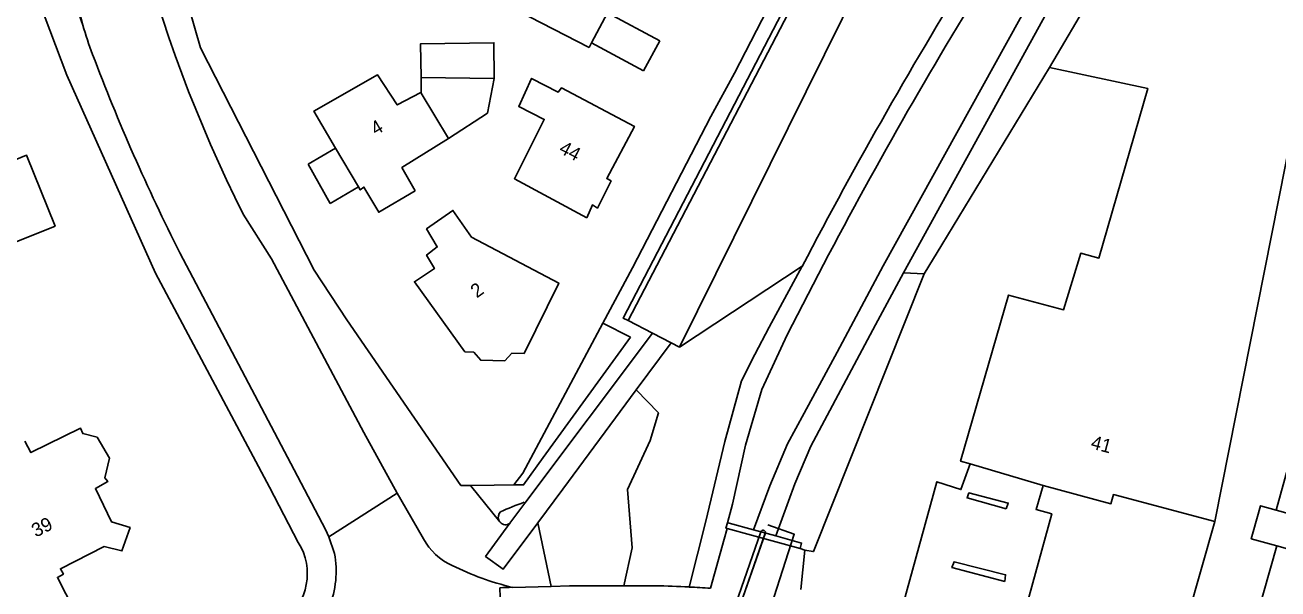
# Model space of a CAD drawing. Extents: x 194485 to 197793, y 468269 to 470822.
# Drawn here: x 194667.8 to 194777.6, y 470049.6 to 470099 of the extents above; entities that cross this region are included whole.
import ezdxf

# ---------------------------------------------------------------- set-up
doc = ezdxf.new("R2010")
doc.units = 0
for name, color, linetype in [('BGT grensvlak begroeid terreindeel', 7, 'Continuous'), ('BGT grensvlak gebouwinstallatie plus 1', 7, 'Continuous'), ('BGT grensvlak kunstwerkdeel uitbreiding populatie min 1', 7, 'Continuous'), ('BGT grensvlak onbegroeid terreindeel', 7, 'Continuous'), ('BGT grensvlak ondersteunend waterdeel LR', 7, 'Continuous'), ('BGT grensvlak pand op maaiveld', 7, 'Continuous'), ('BGT grensvlak scheiding', 7, 'Continuous'), ('BGT grensvlak waterdeel', 7, 'Continuous'), ('BGT grensvlak wegdeel', 7, 'Continuous'), ('BGT lijnelement kunstwerkdeel uitbreiding populatie duiker', 7, 'Continuous'), ('BGT tekst huisnummerreeks', 7, 'Continuous')]:
    doc.layers.add(name, color=color, linetype=linetype)

msp = doc.modelspace()

# ---------------------------------------------------------------- linework, layer by layer
at = {"layer": 'BGT grensvlak begroeid terreindeel'}
msp.add_line((194725.17, 470070.76), (194735.93, 470077.85), dxfattribs=at)
msp.add_lwpolyline([(194720.29, 470049.82), (194721, 470053.17), (194720.61, 470058.28), (194722.58, 470062.58), (194723.32, 470064.99), (194721.36, 470067)], dxfattribs=at)
at = {"layer": 'BGT grensvlak gebouwinstallatie plus 1'}
for p, q in [((194723.44, 470097.62), (194718.86, 470100.08)), ((194717.45, 470097.44), (194722.02, 470094.98)), ((194722.02, 470094.98), (194723.44, 470097.62)), ((194702.52, 470094.4), (194702.52, 470093.04)), ((194708.34, 470091.28), (194708.92, 470094.31)), ((194704.9, 470089.04), (194708.34, 470091.28)), ((194695.01, 470088.22), (194692.6, 470086.81)), ((194692.6, 470086.81), (194694.52, 470083.36)), ((194694.52, 470083.36), (194697.01, 470084.82))]:
    msp.add_line(p, q, dxfattribs=at)
msp.add_lwpolyline([(194757.04, 470058.61), (194756.43, 470056.53), (194757.8, 470056.13), (194754.93, 470045.73), (194744.79, 470048.32), (194747.73, 470058.95), (194749.83, 470058.27), (194750.64, 470060.52)], dxfattribs=at)
at = {"layer": 'BGT grensvlak kunstwerkdeel uitbreiding populatie min 1'}
msp.add_lwpolyline([(194724.26, 470031.41), (194732.3, 470054.57), (194732.32, 470054.6), (194732.34, 470054.64), (194732.37, 470054.66), (194732.4, 470054.68), (194732.44, 470054.7), (194732.48, 470054.7), (194732.52, 470054.7), (194732.56, 470054.69), (194732.59, 470054.67), (194732.62, 470054.65), (194732.65, 470054.62), (194732.67, 470054.59), (194732.69, 470054.55), (194732.69, 470054.51), (194732.69, 470054.47), (194732.68, 470054.44), (194724.64, 470031.28)], dxfattribs=at)
at = {"layer": 'BGT grensvlak onbegroeid terreindeel'}
msp.add_line((194736.91, 470052.85), (194746.62, 470077.18), dxfattribs=at)
for points in [[(194757.6, 470095.27), (194748.16, 470079.72), (194746.62, 470077.18)], [(194718.45, 470072.86), (194711.44, 470059.71), (194710.63, 470058.67)], [(194753.79, 470056.57), (194753.98, 470057.08), (194750.54, 470057.97), (194750.37, 470057.53), (194753.79, 470056.57)], [(194736.15, 470052.96), (194736.88, 470052.83), (194736.91, 470052.85)], [(194753.7, 470050.2), (194753.75, 470050.8), (194749.24, 470051.94), (194749.05, 470051.44), (194753.7, 470050.2)]]:
    msp.add_lwpolyline(points, dxfattribs=at)
at = {"layer": 'BGT grensvlak ondersteunend waterdeel LR'}
msp.add_line((194744.81, 470077.26), (194746.62, 470077.18), dxfattribs=at)
at = {"layer": 'BGT grensvlak pand op maaiveld'}
for p, q in [((194757.6, 470095.27), (194762.34, 470103.37)), ((194717.45, 470097.44), (194718.86, 470100.08)), ((194717.23, 470097.03), (194717.45, 470097.44)), ((194702.52, 470094.4), (194708.92, 470094.31)), ((194704.9, 470089.04), (194702.52, 470093.04)), ((194695.01, 470088.22), (194697.01, 470084.82)), ((194711.53, 470070.2), (194710.45, 470070.23)), ((194757.04, 470058.61), (194750.64, 470060.52))]:
    msp.add_line(p, q, dxfattribs=at)
for points in [[(194718.86, 470100.08), (194712.57, 470103.25), (194711, 470100.25), (194717.23, 470097.03)], [(194708.92, 470094.31), (194708.89, 470097.45), (194702.45, 470097.35), (194702.52, 470094.4)], [(194750.64, 470060.52), (194749.8, 470060.77), (194754.02, 470075.32), (194758.83, 470074.04), (194760.34, 470078.99), (194761.94, 470078.57), (194766.22, 470093.45), (194757.6, 470095.27)], [(194702.52, 470093.04), (194702.49, 470093.08), (194700.42, 470092), (194698.67, 470094.64), (194693.11, 470091.46), (194695.01, 470088.22)], [(194717.03, 470082.11), (194717.52, 470083.23), (194717.97, 470082.95), (194719.17, 470085.34), (194718.79, 470085.54), (194721.21, 470090.12), (194714.82, 470093.5), (194714.53, 470093.13), (194712.2, 470094.32), (194711.07, 470091.85), (194713.31, 470090.72), (194710.69, 470085.52), (194717.03, 470082.11)], [(194701.99, 470084.47), (194700.83, 470086.51), (194704.9, 470089.04)], [(194778.61, 470088.47), (194778.31, 470086.88), (194772.09, 470055.46)], [(194666.76, 470074.86), (194664.92, 470079.18), (194670.42, 470081.37), (194667.9, 470087.6), (194664.34, 470086.13), (194664.56, 470085.52), (194659.8, 470083.49), (194661.95, 470078.2), (194656.62, 470075.8)], [(194697.01, 470084.82), (194697.17, 470084.54), (194697.49, 470084.79), (194698.8, 470082.58), (194701.99, 470084.47)], [(194707.13, 470070.32), (194706.35, 470070.34), (194701.92, 470076.49), (194703.67, 470077.65), (194702.99, 470078.83), (194703.93, 470079.55), (194702.99, 470081.13), (194705.29, 470082.75), (194706.93, 470080.4), (194714.57, 470076.37), (194711.53, 470070.2)], [(194707.13, 470070.32), (194707.73, 470069.61), (194709.84, 470069.55), (194710.45, 470070.23)], [(194667.77, 470062.52), (194668.3, 470061.51), (194672.65, 470063.65), (194672.84, 470063.17), (194674.1, 470062.86), (194675.19, 470061.03), (194674.79, 470059.29), (194675.04, 470058.96), (194673.96, 470058.36), (194675.35, 470055.44), (194676.99, 470054.94), (194676.27, 470052.89), (194674.73, 470053.26), (194670.89, 470051.33), (194671.15, 470050.86), (194670.62, 470050.56), (194672.08, 470047.7), (194668.09, 470045.68), (194666.81, 470048.59)], [(194667.77, 470062.52), (194668.3, 470061.51), (194672.65, 470063.65), (194672.84, 470063.17), (194674.1, 470062.86), (194675.19, 470061.03), (194674.79, 470059.29), (194675.04, 470058.96), (194673.96, 470058.36), (194675.35, 470055.44), (194676.99, 470054.94), (194676.27, 470052.89), (194674.73, 470053.26), (194670.89, 470051.33), (194671.15, 470050.86), (194670.62, 470050.56), (194672.08, 470047.7), (194668.09, 470045.68), (194666.81, 470048.59)], [(194772.09, 470055.46), (194763.2, 470057.83), (194762.98, 470057.03), (194757.04, 470058.61)]]:
    msp.add_lwpolyline(points, dxfattribs=at)
at = {"layer": 'BGT grensvlak scheiding'}
for p, q in [((194735.75, 470053.1), (194729.35, 470054.84)), ((194731.66, 470054.73), (194733.61, 470054.2))]:
    msp.add_line(p, q, dxfattribs=at)
for points in [[(194729.37, 470055.36), (194729.23, 470054.87), (194729.35, 470054.84)], [(194731.66, 470054.73), (194729.51, 470055.32), (194729.37, 470055.36)], [(194733.61, 470054.2), (194735.87, 470053.57), (194735.75, 470053.1)]]:
    msp.add_lwpolyline(points, dxfattribs=at)
at = {"layer": 'BGT grensvlak waterdeel'}
for p, q in [((194743.02, 470077.9), (194763.1, 470114.14)), ((194744.81, 470077.26), (194764.66, 470113.36))]:
    msp.add_line(p, q, dxfattribs=at)
for points in [[(194731.66, 470054.73), (194733.07, 470058.6), (194734.63, 470062.27), (194736.08, 470064.98), (194739, 470070.33), (194743.02, 470077.9)], [(194733.61, 470054.2), (194735.27, 470058.78), (194736.68, 470062.08), (194739.3, 470067.01), (194742.35, 470072.72), (194744.81, 470077.26)]]:
    msp.add_lwpolyline(points, dxfattribs=at)
at = {"layer": 'BGT grensvlak wegdeel'}
for p, q in [((194672.85, 470099), (194668.91, 470115.35)), ((194777.47, 470056.47), (194785.35, 470085.04)), ((194681.36, 470079.02), (194691.38, 470060)), ((194681.36, 470079.02), (194691.38, 470060)), ((194696.01, 470073.14), (194705.98, 470058.61)), ((194718.45, 470072.86), (194720.86, 470071.62)), ((194720.66, 470073.08), (194722.8, 470071.98)), ((194711.6, 470057.08), (194722.8, 470071.98)), ((194713.22, 470061.09), (194720.86, 470071.62)), ((194722.8, 470071.98), (194724.43, 470071.14)), ((194721.36, 470067), (194724.43, 470071.14)), ((194724.43, 470071.14), (194725.17, 470070.76)), ((194714.94, 470058.29), (194721.36, 470067)), ((194697.5, 470063.28), (194700.41, 470057.94)), ((194691.74, 470053.62), (194689.22, 470058.48)), ((194691.74, 470053.62), (194689.22, 470058.48)), ((194705.98, 470058.61), (194706.85, 470058.62)), ((194706.85, 470058.62), (194708.9, 470058.65)), ((194706.85, 470058.62), (194709.4, 470055.44)), ((194708.9, 470058.65), (194710.63, 470058.67)), ((194700.41, 470057.94), (194694.43, 470054.13)), ((194712.75, 470055.36), (194714.94, 470058.29)), ((194711.6, 470057.08), (194710.3, 470055.32)), ((194711.55, 470057.16), (194711.6, 470057.08)), ((194777.47, 470056.47), (194781.08, 470055.45)), ((194709.4, 470055.44), (194709.42, 470055.4)), ((194713.92, 470049.78), (194712.75, 470055.36)), ((194727.46, 470055.5), (194726.01, 470049.72)), ((194772.09, 470055.46), (194768.7, 470043.52)), ((194694.43, 470054.13), (194694.91, 470052.66)), ((194694.43, 470054.13), (194694.91, 470052.66)), ((194736.15, 470052.96), (194735.75, 470053.1)), ((194735.79, 470049.49), (194736.15, 470052.96)), ((194777.54, 470053.33), (194774.58, 470042.9)), ((194777.54, 470053.33), (194780.27, 470052.57)), ((194709.43, 470048.84), (194709.4, 470049.65)), ((194713.92, 470049.78), (194710.51, 470049.69))]:
    msp.add_line(p, q, dxfattribs=at)
for points in [[(194696.01, 470073.14), (194693.13, 470077.51), (194683.18, 470096.99), (194679.88, 470108.39), (194679.16, 470111.8), (194677.42, 470121.59), (194676.5, 470131.68), (194676.34, 470138.79), (194676.65, 470148.24), (194677.32, 470157.81), (194678.33, 470164.6), (194679.43, 470173.22), (194681.09, 470183.46), (194683.7, 470197.19), (194687.3, 470213.24), (194688.11, 470217.15), (194690.16, 470224.82), (194693.77, 470236.11), (194697.78, 470246.83), (194699.13, 470250), (194709.7, 470275.65), (194716.32, 470292.04), (194723.12, 470308.96)], [(194718.45, 470072.86), (194721.03, 470077.72), (194727.92, 470090.98), (194729.99, 470094.77), (194749.21, 470132.1)], [(194720.66, 470073.08), (194739.39, 470109.08), (194744.75, 470119.44), (194751.26, 470132.02)], [(194725.17, 470070.76), (194744.22, 470109.24), (194744.59, 470109.08)], [(194737.5, 470106.52), (194720.21, 470073.31), (194720.66, 470073.08)], [(194669.47, 470099.86), (194671.46, 470094.6), (194679.21, 470077.25), (194689.22, 470058.48)], [(194669.47, 470099.86), (194671.46, 470094.6), (194679.21, 470077.25), (194689.22, 470058.48)], [(194697.5, 470063.28), (194689.38, 470078.51), (194686.91, 470082.41)], [(194727.46, 470055.5), (194729.14, 470062.48), (194730.59, 470067.81), (194731.77, 470070.11), (194733.01, 470072.52), (194735.93, 470077.85)], [(194737.35, 470077.15), (194734.59, 470071.84), (194732.39, 470067.05), (194730.95, 470062.17), (194729.81, 470056.98), (194729.37, 470055.36)], [(194713.22, 470061.09), (194711.49, 470058.68), (194710.88, 470058.67), (194710.63, 470058.67)], [(194691.38, 470060), (194694.13, 470054.76), (194694.43, 470054.13)], [(194691.38, 470060), (194694.13, 470054.76), (194694.43, 470054.13)], [(194702.71, 470053.95), (194701.18, 470056.65), (194700.41, 470057.94)], [(194777.47, 470056.47), (194776.11, 470056.85), (194775.46, 470054.56), (194775.29, 470053.96), (194777.54, 470053.33)], [(194710.3, 470055.32), (194708.16, 470052.41), (194709.7, 470051.28), (194712.75, 470055.36)], [(194727.87, 470049.61), (194729.08, 470053.93), (194729.35, 470054.84)], [(194720.29, 470049.82), (194715.52, 470049.83), (194713.92, 470049.78)], [(194720.29, 470049.82), (194723.07, 470049.82), (194723.04, 470049.82)]]:
    msp.add_lwpolyline(points, dxfattribs=at)
for centre, radius, start, end in [((194799.24, 470138.71), 125.65, 182.0727, 206.6229), ((194652.66, 470092.29), 21.27, 18.3828, 40.9739), ((194652.66, 470092.29), 21.27, 18.3828, 40.9739), ((195095, 469890.79), 404.87, 148.1238, 152.4834), ((195094.63, 469891), 402.87, 148.1205, 152.4789), ((194704.49, 470108.02), 32.9, 195.9054, 200.6591), ((194704.49, 470108.02), 32.9, 195.9054, 200.6591), ((194840.28, 470159.36), 178.07, 200.702, 206.8188), ((194840.28, 470159.36), 178.07, 200.702, 206.8188), ((194709.97, 470055.84), 0.701, 136.803, 201.9763), ((194720.73, 470031.23), 27.5, 109.4944, 114.1933), ((194709.92, 470055.82), 0.646, 202.2929, 216.578), ((194709.91, 470055.82), 0.636, 220.4622, 308.2072), ((194687.4, 470050.88), 5.13, 306.612, 32.2547), ((194687.4, 470050.88), 5.13, 306.612, 32.2547), ((194707.49, 470056.55), 5.44, 208.5596, 245.4), ((194686.61, 470051.1), 8.45, 338.2479, 10.6525), ((194686.61, 470051.1), 8.45, 338.2479, 10.6525), ((194716.53, 470074.51), 25.54, 243.742, 256.3858), ((194714.76, 469908.79), 140.97, 91.7272, 92.1802), ((194721.15, 469949.75), 100.1, 87.2185, 88.9156), ((194721.09, 469949.68), 100.16, 86.1178, 87.1853)]:
    msp.add_arc(centre, radius, start, end, dxfattribs=at)
at = {"layer": 'BGT lijnelement kunstwerkdeel uitbreiding populatie duiker'}
msp.add_line((194724.59, 470031.27), (194732.7, 470054.48), dxfattribs=at)
msp.add_lwpolyline([(194732.36, 470044.81), (194732.44, 470045.7), (194735.23, 470054.35), (194732.92, 470055.18)], dxfattribs=at)

# ---------------------------------------------------------------- texts
at = {"layer": 'BGT tekst huisnummerreeks'}
for s, rotation, p in [('4', 30.4, (194698.53, 470089.29)), ('44', 332.4, (194714.51, 470087.85)), ('2', 35.8, (194707.39, 470075.02)), ('41', 345.1, (194761.15, 470061.89)), ('39', 26.7, (194668.73, 470054.05))]:
    msp.add_text(s, height=1.2, rotation=rotation, dxfattribs=at).set_placement(p)

doc.saveas('drawing.dxf')
